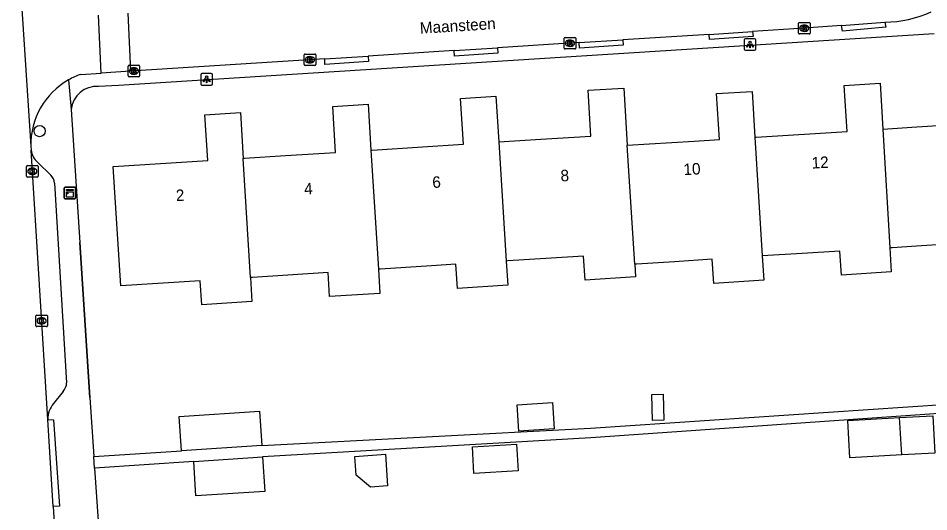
# Model space of a CAD drawing. Extents: x 159628 to 160723, y 388176 to 389416.
# Drawn here: x 160515.5 to 160594.8, y 388384.7 to 388427.7 of the extents above; entities that cross this region are included whole.
import ezdxf

# ---------------------------------------------------------------- set-up
doc = ezdxf.new("R2010")
doc.units = 0
for name, color, linetype in [('IMGEO_Boom', 7, 'Continuous'), ('IMGEO_Kast', 7, 'Continuous'), ('IMGEO_Kolk', 7, 'Continuous'), ('IMGEO_Lichtpunt', 7, 'Continuous'), ('IMGEO_Muur', 7, 'Continuous'), ('IMGEO_Openbare_ruimte_label', 7, 'Continuous'), ('IMGEO_Pand', 7, 'Continuous'), ('IMGEO_Pand_nummerreeks', 7, 'Continuous'), ('IMGEO_Rijbaan_lokaal_gesloten', 7, 'Continuous'), ('IMGEO_Rijbaan_lokaal_open', 7, 'Continuous'), ('IMGEO_Voetpad_open', 7, 'Continuous')]:
    doc.layers.add(name, color=color, linetype=linetype)

msp = doc.modelspace()

# ---------------------------------------------------------------- linework, layer by layer
at = {"layer": 'IMGEO_Boom'}
msp.add_circle((160517.35, 388417.866), 0.489, dxfattribs=at)
at = {"layer": 'IMGEO_Kast'}
for p, q in [((160519.488, 388412.053), (160519.488, 388412.894)), ((160519.488, 388412.894), (160519.488, 388412.053)), ((160519.563, 388412.978), (160520.404, 388412.978)), ((160520.404, 388412.978), (160519.563, 388412.978)), ((160520.488, 388412.903), (160520.488, 388412.062)), ((160520.488, 388412.062), (160520.488, 388412.903)), ((160520.413, 388411.978), (160519.572, 388411.978)), ((160519.572, 388411.978), (160520.413, 388411.978))]:
    msp.add_line(p, q, dxfattribs=at)
for points in [[(160519.683, 388412.768), (160520.283, 388412.768), (160520.283, 388412.683), (160519.683, 388412.683), (160519.683, 388412.768)], [(160519.683, 388412.593), (160520.283, 388412.593), (160520.283, 388412.104), (160519.683, 388412.104), (160519.683, 388412.593)]]:
    msp.add_lwpolyline(points, dxfattribs=at)
msp.add_circle((160519.767, 388412.442), 0.0377, dxfattribs=at)
for centre, start, end in [((160519.566, 388412.9), 92.4484, 184.28452), ((160519.566, 388412.9), 92.4484, 184.28452), ((160520.41, 388412.9), 2.4484, 94.28452), ((160520.41, 388412.9), 2.4484, 94.28452), ((160519.566, 388412.056), 182.4484, 274.28452), ((160519.566, 388412.056), 182.4484, 274.28452), ((160520.41, 388412.056), 272.4484, 4.28452), ((160520.41, 388412.056), 272.4484, 4.28452)]:
    msp.add_arc(centre, 0.0779, start, end, dxfattribs=at)
at = {"layer": 'IMGEO_Kolk'}
for p, q in [((160583.438, 388426.403), (160583.438, 388427.255)), ((160583.513, 388427.329), (160584.365, 388427.329)), ((160583.926, 388427.109), (160583.951, 388427.109)), ((160584.439, 388427.255), (160584.439, 388426.403)), ((160563.105, 388426.023), (160563.957, 388426.023)), ((160584.365, 388426.329), (160583.513, 388426.329)), ((160583.949, 388426.549), (160583.924, 388426.549)), ((160563.03, 388425.097), (160563.03, 388425.949)), ((160563.541, 388425.243), (160563.516, 388425.243)), ((160563.518, 388425.803), (160563.543, 388425.803)), ((160564.031, 388425.949), (160564.031, 388425.097)), ((160540.393, 388423.655), (160540.393, 388424.507)), ((160540.468, 388424.581), (160541.32, 388424.581)), ((160541.394, 388424.507), (160541.394, 388423.655)), ((160563.957, 388425.023), (160563.105, 388425.023)), ((160525.133, 388423.604), (160525.985, 388423.604)), ((160540.904, 388423.801), (160540.879, 388423.801)), ((160540.881, 388424.361), (160540.906, 388424.361)), ((160525.058, 388422.678), (160525.058, 388423.53)), ((160525.569, 388422.824), (160525.544, 388422.824)), ((160525.546, 388423.384), (160525.571, 388423.384)), ((160526.059, 388423.53), (160526.059, 388422.678)), ((160541.32, 388423.581), (160540.468, 388423.581)), ((160525.985, 388422.604), (160525.133, 388422.604)), ((160516.216, 388413.943), (160516.216, 388414.795)), ((160516.291, 388414.869), (160517.143, 388414.869)), ((160516.727, 388414.089), (160516.702, 388414.089)), ((160516.704, 388414.649), (160516.729, 388414.649)), ((160517.217, 388414.795), (160517.217, 388413.943)), ((160517.143, 388413.869), (160516.291, 388413.869)), ((160517.025, 388400.914), (160517.025, 388401.766)), ((160517.1, 388401.84), (160517.952, 388401.84)), ((160517.513, 388401.62), (160517.538, 388401.62)), ((160518.026, 388401.766), (160518.026, 388400.914)), ((160517.952, 388400.84), (160517.1, 388400.84)), ((160517.536, 388401.06), (160517.511, 388401.06))]:
    msp.add_line(p, q, dxfattribs=at)
for points in [[(160583.438, 388426.403), (160583.438, 388427.255)], [(160583.513, 388427.329), (160584.365, 388427.329)], [(160583.759, 388427.029), (160583.882, 388427.029), (160583.882, 388426.878), (160584.012, 388427.029), (160584.176, 388427.029), (160584.03, 388426.878), (160584.183, 388426.629), (160584.031, 388426.629), (160583.946, 388426.793), (160583.882, 388426.726), (160583.882, 388426.629), (160583.759, 388426.629), (160583.759, 388427.029)], [(160584.439, 388427.255), (160584.439, 388426.403)], [(160563.105, 388426.023), (160563.957, 388426.023)], [(160584.365, 388426.329), (160583.513, 388426.329)], [(160563.03, 388425.097), (160563.03, 388425.949)], [(160563.351, 388425.723), (160563.474, 388425.723), (160563.474, 388425.572), (160563.604, 388425.723), (160563.768, 388425.723), (160563.622, 388425.572), (160563.775, 388425.323), (160563.623, 388425.323), (160563.538, 388425.487), (160563.474, 388425.42), (160563.474, 388425.323), (160563.351, 388425.323), (160563.351, 388425.723)], [(160564.031, 388425.949), (160564.031, 388425.097)], [(160540.393, 388423.655), (160540.393, 388424.507)], [(160540.468, 388424.581), (160541.32, 388424.581)], [(160541.394, 388424.507), (160541.394, 388423.655)], [(160563.957, 388425.023), (160563.105, 388425.023)], [(160525.133, 388423.604), (160525.985, 388423.604)], [(160540.714, 388424.281), (160540.837, 388424.281), (160540.837, 388424.13), (160540.967, 388424.281), (160541.131, 388424.281), (160540.985, 388424.13), (160541.138, 388423.881), (160540.986, 388423.881), (160540.901, 388424.045), (160540.837, 388423.978), (160540.837, 388423.881), (160540.714, 388423.881), (160540.714, 388424.281)], [(160525.058, 388422.678), (160525.058, 388423.53)], [(160525.379, 388423.304), (160525.502, 388423.304), (160525.502, 388423.153), (160525.632, 388423.304), (160525.796, 388423.304), (160525.65, 388423.153), (160525.803, 388422.904), (160525.651, 388422.904), (160525.566, 388423.068), (160525.502, 388423.001), (160525.502, 388422.904), (160525.379, 388422.904), (160525.379, 388423.304)], [(160526.059, 388423.53), (160526.059, 388422.678)], [(160541.32, 388423.581), (160540.468, 388423.581)], [(160525.985, 388422.604), (160525.133, 388422.604)], [(160516.216, 388413.943), (160516.216, 388414.795)], [(160516.291, 388414.869), (160517.143, 388414.869)], [(160516.537, 388414.569), (160516.66, 388414.569), (160516.66, 388414.418), (160516.79, 388414.569), (160516.954, 388414.569), (160516.808, 388414.418), (160516.961, 388414.169), (160516.809, 388414.169), (160516.724, 388414.333), (160516.66, 388414.266), (160516.66, 388414.169), (160516.537, 388414.169), (160516.537, 388414.569)], [(160517.217, 388414.795), (160517.217, 388413.943)], [(160517.143, 388413.869), (160516.291, 388413.869)], [(160517.025, 388400.914), (160517.025, 388401.766)], [(160517.1, 388401.84), (160517.952, 388401.84)], [(160517.346, 388401.54), (160517.469, 388401.54), (160517.469, 388401.389), (160517.599, 388401.54), (160517.763, 388401.54), (160517.617, 388401.389), (160517.77, 388401.14), (160517.618, 388401.14), (160517.533, 388401.304), (160517.469, 388401.237), (160517.469, 388401.14), (160517.346, 388401.14), (160517.346, 388401.54)], [(160518.026, 388401.766), (160518.026, 388400.914)], [(160517.952, 388400.84), (160517.1, 388400.84)]]:
    msp.add_lwpolyline(points, dxfattribs=at)
for centre, start, end in [((160583.515, 388427.253), 91.55205, 178.44795), ((160583.515, 388427.253), 91.55205, 178.44795), ((160584.363, 388427.253), 1.55205, 88.44795), ((160584.363, 388427.253), 1.55205, 88.44795), ((160563.107, 388425.947), 91.55205, 178.44795), ((160563.107, 388425.947), 91.55205, 178.44795), ((160563.955, 388425.947), 1.55205, 88.44795), ((160563.955, 388425.947), 1.55205, 88.44795), ((160583.515, 388426.405), 181.55205, 268.44795), ((160583.515, 388426.405), 181.55205, 268.44795), ((160584.363, 388426.405), 271.55205, 358.44795), ((160584.363, 388426.405), 271.55205, 358.44795), ((160540.47, 388424.505), 91.55205, 178.44795), ((160540.47, 388424.505), 91.55205, 178.44795), ((160541.318, 388424.505), 1.55205, 88.44795), ((160541.318, 388424.505), 1.55205, 88.44795), ((160563.107, 388425.099), 181.55205, 268.44795), ((160563.107, 388425.099), 181.55205, 268.44795), ((160563.955, 388425.099), 271.55205, 358.44795), ((160563.955, 388425.099), 271.55205, 358.44795), ((160525.135, 388423.528), 91.55205, 178.44795), ((160525.135, 388423.528), 91.55205, 178.44795), ((160525.983, 388423.528), 1.55205, 88.44795), ((160525.983, 388423.528), 1.55205, 88.44795), ((160540.47, 388423.657), 181.55205, 268.44795), ((160540.47, 388423.657), 181.55205, 268.44795), ((160541.318, 388423.657), 271.55205, 358.44795), ((160541.318, 388423.657), 271.55205, 358.44795), ((160525.135, 388422.68), 181.55205, 268.44795), ((160525.135, 388422.68), 181.55205, 268.44795), ((160525.983, 388422.68), 271.55205, 358.44795), ((160525.983, 388422.68), 271.55205, 358.44795), ((160516.293, 388414.793), 91.55205, 178.44795), ((160516.293, 388414.793), 91.55205, 178.44795), ((160517.141, 388414.793), 1.55205, 88.44795), ((160517.141, 388414.793), 1.55205, 88.44795), ((160516.293, 388413.945), 181.55205, 268.44795), ((160516.293, 388413.945), 181.55205, 268.44795), ((160517.141, 388413.945), 271.55205, 358.44795), ((160517.141, 388413.945), 271.55205, 358.44795), ((160517.102, 388401.764), 91.55205, 178.44795), ((160517.102, 388401.764), 91.55205, 178.44795), ((160517.95, 388401.764), 1.55205, 88.44795), ((160517.95, 388401.764), 1.55205, 88.44795), ((160517.102, 388400.916), 181.55205, 268.44795), ((160517.102, 388400.916), 181.55205, 268.44795), ((160517.95, 388400.916), 271.55205, 358.44795), ((160517.95, 388400.916), 271.55205, 358.44795)]:
    msp.add_arc(centre, 0.0765, start, end, dxfattribs=at)
for centre, major_axis, ratio, start_param, end_param in [((160583.925, 388426.829), (-0.387, 0.002), 0.722429, 4.712389, 7.853982), ((160583.95, 388426.829), (-0.39, 0.002), 0.717154, 1.570796, 4.712389), ((160563.517, 388425.523), (-0.387, 0.002), 0.722429, 4.712389, 7.853982), ((160563.542, 388425.523), (-0.39, 0.002), 0.717154, 1.570796, 4.712389), ((160540.88, 388424.081), (-0.387, 0.002), 0.722429, 4.712389, 7.853982), ((160540.905, 388424.081), (-0.39, 0.002), 0.717154, 1.570796, 4.712389), ((160525.545, 388423.104), (-0.387, 0.002), 0.722429, 4.712389, 7.853982), ((160525.57, 388423.104), (-0.39, 0.002), 0.717154, 1.570796, 4.712389), ((160516.703, 388414.369), (-0.387, 0.002), 0.722429, 4.712389, 7.853982), ((160516.728, 388414.369), (-0.39, 0.002), 0.717154, 1.570796, 4.712389), ((160517.512, 388401.34), (-0.387, 0.002), 0.722429, 4.712389, 7.853982), ((160517.537, 388401.34), (-0.39, 0.002), 0.717154, 1.570796, 4.712389)]:
    msp.add_ellipse(centre, major_axis=major_axis, ratio=ratio, start_param=start_param, end_param=end_param, dxfattribs=at)
at = {"layer": 'IMGEO_Lichtpunt'}
for p, q in [((160578.712, 388425.818), (160578.712, 388425.011)), ((160578.712, 388425.818), (160578.712, 388425.011)), ((160579.614, 388425.913), (160578.806, 388425.913)), ((160579.614, 388425.913), (160578.806, 388425.913)), ((160579.708, 388425.011), (160579.708, 388425.818)), ((160579.708, 388425.011), (160579.708, 388425.818)), ((160578.806, 388424.917), (160579.614, 388424.917)), ((160578.806, 388424.917), (160579.614, 388424.917)), ((160532.296, 388422.874), (160531.488, 388422.874)), ((160532.296, 388422.874), (160531.488, 388422.874)), ((160531.394, 388422.779), (160531.394, 388421.972)), ((160531.394, 388422.779), (160531.394, 388421.972)), ((160532.39, 388421.972), (160532.39, 388422.779)), ((160532.39, 388421.972), (160532.39, 388422.779)), ((160531.488, 388421.878), (160532.296, 388421.878)), ((160531.488, 388421.878), (160532.296, 388421.878))]:
    msp.add_line(p, q, dxfattribs=at)
for points in [[(160579.086, 388425.482), (160579.125, 388425.454), (160578.937, 388425.192), (160578.899, 388425.219), (160579.086, 388425.482)], [(160579.188, 388425.434), (160579.235, 388425.434), (160579.235, 388425.112), (160579.188, 388425.112), (160579.188, 388425.434)], [(160579.298, 388425.454), (160579.336, 388425.481), (160579.523, 388425.219), (160579.484, 388425.191), (160579.298, 388425.454)], [(160531.768, 388422.443), (160531.807, 388422.415), (160531.619, 388422.153), (160531.581, 388422.18), (160531.768, 388422.443)], [(160531.87, 388422.395), (160531.917, 388422.395), (160531.917, 388422.073), (160531.87, 388422.073), (160531.87, 388422.395)], [(160531.98, 388422.415), (160532.018, 388422.442), (160532.205, 388422.18), (160532.166, 388422.152), (160531.98, 388422.415)]]:
    msp.add_lwpolyline(points, dxfattribs=at)
for centre in [(160579.211, 388425.616), (160531.893, 388422.577)]:
    msp.add_circle(centre, 0.0994, dxfattribs=at)
for centre, start, end in [((160578.806, 388425.818), 90, 180), ((160578.806, 388425.818), 90, 180), ((160579.614, 388425.818), 0, 90), ((160579.614, 388425.818), 0, 90), ((160578.806, 388425.011), 180, 270), ((160578.806, 388425.011), 180, 270), ((160579.614, 388425.011), 270, 0), ((160579.614, 388425.011), 270, 360), ((160531.488, 388422.779), 90, 180), ((160531.488, 388422.779), 90, 180), ((160532.296, 388422.779), 0, 90), ((160532.296, 388422.779), 0, 90), ((160531.488, 388421.972), 180, 270), ((160531.488, 388421.972), 180, 270), ((160532.296, 388421.972), 270, 0), ((160532.296, 388421.972), 270, 360)]:
    msp.add_arc(centre, 0.0946, start, end, dxfattribs=at)
at = {"layer": 'IMGEO_Muur'}
msp.add_lwpolyline([(160521.731, 388394.661), (160520.849, 388408.172)], dxfattribs=at)
at = {"layer": 'IMGEO_Pand'}
for points in [[(160579.645, 388417.341), (160579.744, 388417.347), (160587.664, 388417.848), (160587.413, 388421.834), (160590.542, 388422.033), (160590.776, 388418.042)], [(160590.776, 388418.042), (160593.733, 388418.235), (160598.792, 388418.565), (160598.532, 388422.555), (160601.635, 388422.75)], [(160557.336, 388416.924), (160560.99, 388417.155), (160565.362, 388417.432), (160565.11, 388421.422), (160568.21, 388421.619), (160568.523, 388416.631)], [(160568.523, 388416.631), (160574.347, 388417), (160576.55, 388417.14), (160576.298, 388421.13), (160579.402, 388421.326), (160579.645, 388417.341)], [(160546.206, 388416.211), (160546.321, 388416.218), (160550.703, 388416.499), (160554.255, 388416.727), (160553.999, 388420.719), (160557.089, 388420.913), (160557.336, 388416.924)], [(160535.076, 388415.495), (160535.192, 388415.503), (160538.762, 388415.732), (160543.126, 388416.012), (160542.87, 388420.004), (160545.96, 388420.202), (160546.206, 388416.211)], [(160535.712, 388405.117), (160535.84, 388403.021), (160531.471, 388402.741), (160531.336, 388404.836), (160524.43, 388404.393), (160523.764, 388414.771), (160531.997, 388415.298), (160531.741, 388419.289), (160534.831, 388419.487), (160535.076, 388415.495)], [(160590.776, 388418.042), (160591.382, 388407.697)], [(160579.645, 388417.341), (160580.277, 388407.005)], [(160557.336, 388416.924), (160557.979, 388406.55)], [(160569.174, 388406.268), (160568.523, 388416.631)], [(160546.206, 388416.211), (160546.845, 388405.834)], [(160535.712, 388405.117), (160535.076, 388415.495)], [(160602.794, 388406.309), (160598.31, 388406.029), (160598.174, 388408.133), (160593.722, 388407.847), (160591.587, 388407.71), (160591.382, 388407.697)], [(160569.174, 388406.268), (160569.243, 388405.17), (160564.858, 388404.888), (160564.723, 388406.983), (160561.429, 388406.771), (160558.136, 388406.56), (160557.979, 388406.55)], [(160580.277, 388407.005), (160580.406, 388404.886), (160576.051, 388404.606), (160575.916, 388406.701), (160572.622, 388406.49), (160569.329, 388406.278), (160569.174, 388406.268)], [(160591.382, 388407.697), (160591.505, 388405.6), (160587.18, 388405.322), (160587.045, 388407.417), (160583.751, 388407.205), (160580.277, 388407.005)], [(160557.979, 388406.55), (160558.109, 388404.454), (160553.729, 388404.172), (160553.594, 388406.267), (160551.466, 388406.13), (160547.007, 388405.844), (160546.845, 388405.834)], [(160546.845, 388405.834), (160546.974, 388403.737), (160542.6, 388403.456), (160542.465, 388405.551), (160535.878, 388405.128), (160535.712, 388405.117)], [(160571.644, 388394.96), (160571.718, 388392.691), (160570.728, 388392.659), (160570.653, 388394.927), (160571.644, 388394.96)], [(160529.706, 388390.012), (160529.509, 388393.005), (160536.493, 388393.464), (160536.69, 388390.471)], [(160562.007, 388394.224), (160562.153, 388391.937), (160559.08, 388391.74), (160558.933, 388394.027), (160562.007, 388394.224)], [(160592.444, 388389.659), (160587.917, 388389.413), (160587.74, 388392.673), (160592.219, 388392.916)], [(160592.219, 388392.916), (160595.136, 388393.075), (160595.313, 388389.814), (160592.444, 388389.659)], [(160592.444, 388389.659), (160592.219, 388392.916)], [(160536.69, 388390.471), (160529.706, 388390.012)], [(160558.891, 388390.605), (160559.026, 388388.276), (160555.171, 388388.053), (160555.036, 388390.382), (160558.891, 388390.605)], [(160547.456, 388389.72), (160547.652, 388386.958), (160546.165, 388386.853), (160544.907, 388387.887), (160544.79, 388389.531), (160547.456, 388389.72)], [(160536.755, 388389.483), (160536.952, 388386.49), (160530.965, 388386.096), (160530.768, 388389.089)], [(160530.768, 388389.089), (160536.755, 388389.483)]]:
    msp.add_lwpolyline(points, dxfattribs=at)
at = {"layer": 'IMGEO_Rijbaan_lokaal_gesloten'}
for points in [[(160515.485, 388433.393), (160516.58, 388416.547)], [(160516.58, 388416.547), (160516.6, 388416.221)], [(160518.057, 388392.76), (160516.6, 388416.221)], [(160518.528, 388385.161), (160518.057, 388392.76)], [(160518.528, 388385.161), (160518.943, 388378.448), (160519.22, 388373.807), (160519.307, 388373.009), (160519.408, 388372.214), (160521.368, 388360.083), (160521.911, 388356.453)]]:
    msp.add_lwpolyline(points, dxfattribs=at)
at = {"layer": 'IMGEO_Rijbaan_lokaal_open'}
for points in [[(160522.715, 388422.924), (160522.477, 388427.971)], [(160525.02, 388428.13), (160525.26, 388423.086)], [(160587.17, 388427.056), (160583.939, 388426.83), (160579.442, 388426.54)], [(160587.17, 388427.056), (160590.95, 388427.367)], [(160575.667, 388426.296), (160568.126, 388425.816)], [(160575.667, 388426.296), (160579.442, 388426.54)], [(160564.339, 388425.575), (160557.225, 388425.123)], [(160564.339, 388425.575), (160568.126, 388425.816)], [(160542.187, 388424.165), (160545.973, 388424.406)], [(160553.441, 388424.882), (160545.973, 388424.406)], [(160553.441, 388424.882), (160557.225, 388425.123)], [(160542.187, 388424.165), (160525.26, 388423.086)], [(160520.927, 388422.81), (160522.715, 388422.924)], [(160525.26, 388423.086), (160522.715, 388422.924)]]:
    msp.add_lwpolyline(points, dxfattribs=at)
for centre, radius, start, end in [((160590.971, 388436.758), 9.391, 269.87131, 295.31851), ((160523.086, 388416.666), 6.512, 109.36457, 119.55613), ((160523.085, 388416.672), 6.506, 119.57348, 181.10332)]:
    msp.add_arc(centre, radius, start, end, dxfattribs=at)
at = {"layer": 'IMGEO_Voetpad_open'}
for points in [[(160590.95, 388427.367), (160591.043, 388426.925), (160587.251, 388426.577), (160587.17, 388427.056)], [(160595.247, 388426.341), (160524.215, 388421.845), (160522.486, 388421.748)], [(160579.442, 388426.54), (160579.476, 388426.096), (160575.681, 388425.834), (160575.667, 388426.296)], [(160568.126, 388425.816), (160568.152, 388425.361), (160564.371, 388425.105), (160564.339, 388425.575)], [(160545.973, 388424.406), (160545.991, 388423.935), (160542.186, 388423.683), (160542.187, 388424.165)], [(160557.225, 388425.123), (160557.252, 388424.657), (160553.471, 388424.405), (160553.441, 388424.882)], [(160519.874, 388422.331), (160520.091, 388419.756)], [(160520.091, 388419.756), (160520.849, 388408.172), (160521.731, 388394.661), (160522.068, 388389.513)], [(160517.191, 388415.129), (160518.323, 388414.04)], [(160518.652, 388413.324), (160519.699, 388395.929)], [(160536.69, 388390.471), (160565.317, 388391.995), (160599.857, 388394.307), (160626.356, 388396.282)], [(160519.404, 388395.201), (160518.57, 388394.139)], [(160622.685, 388395.152), (160565.345, 388391.14), (160536.755, 388389.483)], [(160518.057, 388392.76), (160518.557, 388392.732), (160519.08, 388385.199), (160518.528, 388385.161)], [(160522.068, 388389.513), (160529.706, 388390.012)], [(160522.133, 388388.524), (160522.068, 388389.513)], [(160530.768, 388389.089), (160522.133, 388388.524)], [(160522.133, 388388.524), (160522.434, 388383.909), (160523.246, 388371.486), (160523.363, 388369.681), (160524.702, 388358.575)]]:
    msp.add_lwpolyline(points, dxfattribs=at)
for centre, radius, start, end in [((160522.294, 388419.543), 2.213, 85.02025, 174.48256), ((160518.406, 388416.493), 1.827, 188.55352, 228.29177), ((160517.572, 388413.261), 1.082, 3.32529, 46.03201), ((160518.57, 388395.963), 1.13, 317.59688, 358.28559), ((160520.083, 388392.791), 2.026, 138.30289, 180.88584)]:
    msp.add_arc(centre, radius, start, end, dxfattribs=at)

# ---------------------------------------------------------------- texts
at = {"layer": 'IMGEO_Openbare_ruimte_label'}
msp.add_text('Maansteen', height=1, rotation=3.61207, dxfattribs=at).set_placement((160550.488, 388426.343))
at = {"layer": 'IMGEO_Pand_nummerreeks'}
for s, p in [('12', (160584.599, 388414.599)), ('10', (160573.441, 388414.028)), ('8', (160562.737, 388413.481)), ('4', (160540.404, 388412.338)), ('6', (160551.569, 388412.91)), ('2', (160529.237, 388411.767))]:
    msp.add_text(s, height=1, rotation=2.92781, dxfattribs=at).set_placement(p)

doc.saveas('drawing.dxf')
